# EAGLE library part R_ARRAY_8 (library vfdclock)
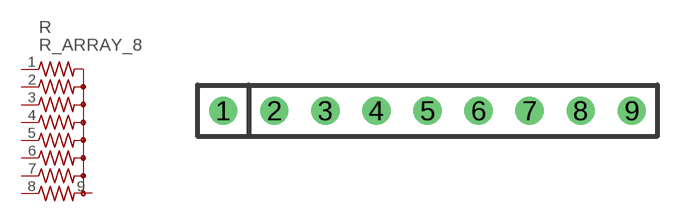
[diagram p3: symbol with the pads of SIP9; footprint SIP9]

Designator prefix R

## R_ARRAY_8  [SIP9]
1  1  pas
2  2  pas
3  3  pas
4  4  pas
5  5  pas
6  6  pas
7  7  pas
8  8  pas
9  COM  pas

## Footprint SIP9 (pad centres in mm)
drill 0.9 round: 1 -10.16,0; 2 -7.62,0; 3 -5.08,0; 4 -2.54,0; 5 0,0; 6 2.54,0; 7 5.08,0; 8 7.62,0; 9 10.16,0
